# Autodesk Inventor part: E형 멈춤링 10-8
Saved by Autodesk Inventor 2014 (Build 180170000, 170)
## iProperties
Created: 2024-08
Part Number: E형 멈춤링 10-8
Material: 일반
Document SubType Name: Modeling
Designer: dg
Density: 1 g/cm^3
Appearance: 기본값
Author: dg
Author: jhkim
Description: 일반용 테이퍼 및 줄어든 횡단면 리테이닝 링 - E-링 외부 시리즈 3CM1 리테이닝 링
Creation Date: 2024-08-09
Sending System: Autodesk Inventor 2025
Preprocessor: ST-DEVELOPER v20
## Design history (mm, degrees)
node "E형 멈춤링 10-81"
body "Solid1"
node "기준1"
